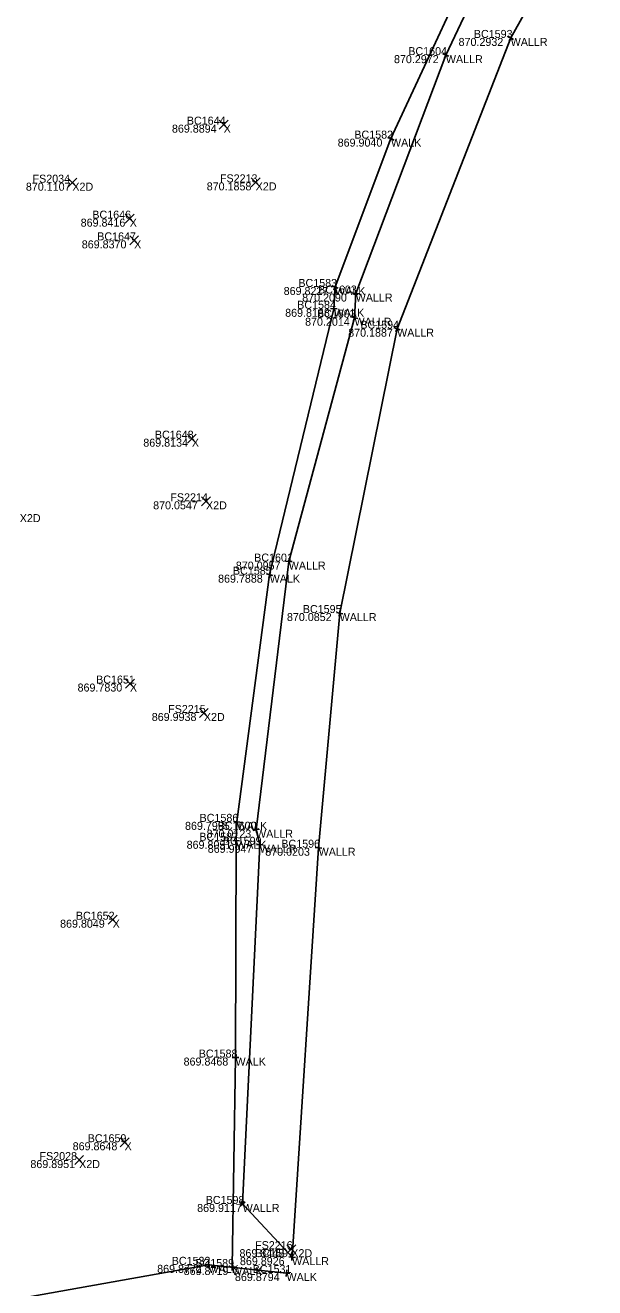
# Model space of a CAD drawing. Extents: x 1479425 to 1480294, y 379351 to 380102.
# Drawn here: x 1479699.88 to 1479704.14, y 379912.39 to 379921.85 of the extents above; entities that cross this region are included whole.
import ezdxf

# ---------------------------------------------------------------- set-up
doc = ezdxf.new("R2010")
doc.units = 0
for name, color, linetype in [('PV_X_Walk', 7, 'Continuous'), ('RD_X_Wall', 7, 'Continuous'), ('SV_X_Random_Point', 7, 'Continuous'), ('SV_X_Shot_Marker', 7, 'Continuous'), ('SV_X_Text_Comment', 7, 'Continuous'), ('SV_X_Text_Elevation', 7, 'Continuous'), ('SV_X_Text_Name', 7, 'Continuous')]:
    doc.layers.add(name, color=color, linetype=linetype)

msp = doc.modelspace()

# ---------------------------------------------------------------- linework, layer by layer
at = {"layer": 'PV_X_Walk'}
for points in [[(1479701.8352, 379912.4997), (1479701.2507, 379912.5611), (1479699.8235, 379912.3065), (1479697.4959, 379911.9204), (1479695.7834, 379911.7114), (1479695.8711, 379913.5546), (1479696.0253, 379915.6699), (1479696.3297, 379917.4434), (1479698.2528, 379916.8723), (1479698.3113, 379916.9697), (1479698.9161, 379918.9097), (1479698.892, 379918.9723), (1479699.4573, 379920.6485), (1479699.5018, 379920.7626), (1479697.5293, 379921.3818), (1479698.4277, 379923.2922)], [(1479703.3879, 379922.6665), (1479702.6175, 379921.0036), (1479702.1988, 379919.8915), (1479702.1896, 379919.7279), (1479701.7088, 379917.7349), (1479701.4627, 379915.8819), (1479701.457, 379915.7401), (1479701.4531, 379914.1148), (1479701.4276, 379912.5449)]]:
    msp.add_lwpolyline(points, dxfattribs=at)
at = {"layer": 'RD_X_Wall'}
msp.add_lwpolyline([(1479707.9477, 379927.6468), (1479706.4736, 379926.2425), (1479705.5301, 379925.1676), (1479704.7565, 379923.9768), (1479703.514, 379921.7583), (1479702.6632, 379919.5789), (1479702.2332, 379917.4471), (1479702.0758, 379915.6878), (1479701.8768, 379912.6189), (1479701.5063, 379913.0175), (1479701.6342, 379915.7099), (1479701.6071, 379915.8229), (1479701.8518, 379917.8328), (1479702.3444, 379919.6609), (1479702.3531, 379919.8421), (1479703.0284, 379921.6293), (1479703.7656, 379923.1882), (1479704.4556, 379924.2246), (1479704.5099, 379924.3288), (1479705.4153, 379925.6855), (1479706.4172, 379926.7904), (1479707.2828, 379927.6042)], dxfattribs=at)
at = {"layer": 'SV_X_Random_Point'}
for p, q in [((1479701.331, 379921.0749), (1479701.3976, 379921.1417)), ((1479701.331, 379921.1417), (1479701.3976, 379921.0749)), ((1479700.1977, 379920.6397), (1479700.2643, 379920.7065)), ((1479700.1977, 379920.7065), (1479700.2643, 379920.6397)), ((1479701.5707, 379920.6422), (1479701.6373, 379920.709)), ((1479701.5707, 379920.709), (1479701.6373, 379920.6422)), ((1479700.6275, 379920.3702), (1479700.6941, 379920.437)), ((1479700.6275, 379920.437), (1479700.6941, 379920.3702)), ((1479700.6603, 379920.2074), (1479700.7269, 379920.2742)), ((1479700.6603, 379920.2742), (1479700.7269, 379920.2074)), ((1479701.0928, 379918.7208), (1479701.1594, 379918.7876)), ((1479701.0928, 379918.7876), (1479701.1594, 379918.7208)), ((1479701.1987, 379918.2513), (1479701.2653, 379918.3181)), ((1479701.1987, 379918.3181), (1479701.2653, 379918.2513)), ((1479700.6289, 379916.8852), (1479700.6955, 379916.952)), ((1479700.6289, 379916.952), (1479700.6955, 379916.8852)), ((1479701.1827, 379916.6647), (1479701.2493, 379916.7315)), ((1479701.1827, 379916.7315), (1479701.2493, 379916.6647)), ((1479700.4993, 379915.1148), (1479700.5659, 379915.1816)), ((1479700.4993, 379915.1816), (1479700.5659, 379915.1148)), ((1479700.5889, 379913.4467), (1479700.6555, 379913.5135)), ((1479700.5889, 379913.5135), (1479700.6555, 379913.4467)), ((1479700.2487, 379913.3131), (1479700.3153, 379913.3799)), ((1479700.2487, 379913.3799), (1479700.3153, 379913.3131)), ((1479701.8377, 379912.6451), (1479701.9043, 379912.7119)), ((1479701.8377, 379912.7119), (1479701.9043, 379912.6451))]:
    msp.add_line(p, q, dxfattribs=at)
at = {"layer": 'SV_X_Shot_Marker'}
for p, q in [((1479703.5358, 379921.7461), (1479703.4922, 379921.7705)), ((1479703.5262, 379921.7801), (1479703.5018, 379921.7365)), ((1479703.514, 379921.7583), (1479703.514, 379921.7583)), ((1479703.005, 379921.6382), (1479703.0518, 379921.6205)), ((1479703.0196, 379921.6059), (1479703.0372, 379921.6527)), ((1479703.0284, 379921.6293), (1479703.0284, 379921.6293)), ((1479702.6402, 379920.9931), (1479702.5948, 379921.0141)), ((1479702.628, 379921.0263), (1479702.607, 379920.9809)), ((1479702.6175, 379921.0036), (1479702.6175, 379921.0036)), ((1479702.2222, 379919.8827), (1479702.1754, 379919.9003)), ((1479702.2076, 379919.9149), (1479702.19, 379919.8681)), ((1479702.1988, 379919.8915), (1479702.1988, 379919.8915)), ((1479702.3281, 379919.8433), (1479702.3781, 379919.8409)), ((1479702.3519, 379919.8171), (1479702.3543, 379919.8671)), ((1479702.3531, 379919.8421), (1479702.3531, 379919.8421)), ((1479702.191, 379919.7529), (1479702.1882, 379919.703)), ((1479702.2146, 379919.7265), (1479702.1646, 379919.7293)), ((1479702.1896, 379919.7279), (1479702.1896, 379919.7279)), ((1479702.3203, 379919.6674), (1479702.3685, 379919.6544)), ((1479702.3379, 379919.6368), (1479702.3509, 379919.6851)), ((1479702.3444, 379919.6609), (1479702.3444, 379919.6609)), ((1479702.6865, 379919.5698), (1479702.6399, 379919.588)), ((1479702.6723, 379919.6022), (1479702.6541, 379919.5556)), ((1479702.6632, 379919.5789), (1479702.6632, 379919.5789)), ((1479701.8488, 379917.808), (1479701.8548, 379917.8576)), ((1479701.7147, 379917.7592), (1479701.7029, 379917.7106)), ((1479701.827, 379917.8358), (1479701.8766, 379917.8298)), ((1479701.8518, 379917.8328), (1479701.8518, 379917.8328)), ((1479701.7331, 379917.7291), (1479701.6845, 379917.7408)), ((1479701.7088, 379917.7349), (1479701.7088, 379917.7349)), ((1479702.2381, 379917.4716), (1479702.2283, 379917.4226)), ((1479702.2577, 379917.4422), (1479702.2087, 379917.4521)), ((1479702.2332, 379917.4471), (1479702.2332, 379917.4471)), ((1479701.4875, 379915.8786), (1479701.4379, 379915.8852)), ((1479701.466, 379915.9067), (1479701.4594, 379915.8571)), ((1479701.4627, 379915.8819), (1479701.4627, 379915.8819)), ((1479701.458, 379915.7651), (1479701.456, 379915.7151)), ((1479701.5828, 379915.8171), (1479701.6314, 379915.8287)), ((1479701.6129, 379915.7986), (1479701.6013, 379915.8472)), ((1479701.6071, 379915.8229), (1479701.6071, 379915.8229)), ((1479701.482, 379915.7391), (1479701.432, 379915.7411)), ((1479701.457, 379915.7401), (1479701.457, 379915.7401)), ((1479701.6092, 379915.7111), (1479701.6592, 379915.7087)), ((1479701.633, 379915.6849), (1479701.6354, 379915.7349)), ((1479701.6342, 379915.7099), (1479701.6342, 379915.7099)), ((1479702.1007, 379915.6856), (1479702.0509, 379915.69)), ((1479702.078, 379915.7127), (1479702.0736, 379915.6629)), ((1479702.0758, 379915.6878), (1479702.0758, 379915.6878)), ((1479701.4781, 379914.1148), (1479701.4281, 379914.1149)), ((1479701.4532, 379914.1398), (1479701.453, 379914.0898)), ((1479701.4531, 379914.1148), (1479701.4531, 379914.1148)), ((1479701.488, 379913.0005), (1479701.5246, 379913.0345)), ((1479701.5233, 379912.9992), (1479701.4893, 379913.0358)), ((1479701.5063, 379913.0175), (1479701.5063, 379913.0175)), ((1479701.8784, 379912.6439), (1479701.8752, 379912.594)), ((1479701.2756, 379912.5585), (1479701.2258, 379912.5637)), ((1479701.2481, 379912.5363), (1479701.2533, 379912.586)), ((1479701.2507, 379912.5611), (1479701.2507, 379912.5611)), ((1479701.4526, 379912.5445), (1479701.4026, 379912.5453)), ((1479701.428, 379912.5699), (1479701.4272, 379912.5199)), ((1479701.4276, 379912.5449), (1479701.4276, 379912.5449)), ((1479701.9017, 379912.6173), (1479701.8518, 379912.6205)), ((1479701.8768, 379912.6189), (1479701.8768, 379912.6189)), ((1479701.8601, 379912.4971), (1479701.8103, 379912.5023)), ((1479701.8326, 379912.4749), (1479701.8378, 379912.5246)), ((1479701.8352, 379912.4997), (1479701.8352, 379912.4997))]:
    msp.add_line(p, q, dxfattribs=at)

# ---------------------------------------------------------------- texts
at = {"layer": 'SV_X_Text_Comment'}
for s, p in [('WALLR', (1479703.514, 379921.6983)), ('WALLR', (1479703.0284, 379921.5693)), ('X', (1479701.3643, 379921.0483)), ('WALK', (1479702.6175, 379920.9436)), ('X2D', (1479700.231, 379920.6131)), ('X2D', (1479701.604, 379920.6156)), ('X', (1479700.6608, 379920.3436)), ('X', (1479700.6936, 379920.1808)), ('WALK', (1479702.1988, 379919.8315)), ('WALLR', (1479702.3531, 379919.7821)), ('WALK', (1479702.1896, 379919.6679)), ('WALLR', (1479702.3444, 379919.6009)), ('WALLR', (1479702.6632, 379919.5189)), ('X', (1479701.1261, 379918.6942)), ('X2D', (1479701.232, 379918.2247)), ('X2D', (1479699.837, 379918.1286)), ('WALLR', (1479701.8518, 379917.7728)), ('WALK', (1479701.7088, 379917.6749)), ('WALLR', (1479702.2332, 379917.3871)), ('X', (1479700.6622, 379916.8586)), ('X2D', (1479701.216, 379916.6381)), ('WALK', (1479701.4627, 379915.8219)), ('WALLR', (1479701.6071, 379915.7629)), ('WALK', (1479701.457, 379915.6801)), ('WALLR', (1479701.6342, 379915.6499)), ('WALLR', (1479702.0758, 379915.6278)), ('X', (1479700.5326, 379915.0882)), ('WALK', (1479701.4531, 379914.0548)), ('X', (1479700.6222, 379913.4201)), ('X2D', (1479700.282, 379913.2865)), ('WALLR', (1479701.5063, 379912.9575)), ('X2D', (1479701.871, 379912.6185)), ('WALK', (1479701.2507, 379912.5011)), ('WALK', (1479701.4276, 379912.4849)), ('WALLR', (1479701.8768, 379912.5589)), ('WALK', (1479701.8352, 379912.4397))]:
    msp.add_text(s, height=0.06, dxfattribs=at).set_placement(p)
at = {"layer": 'SV_X_Text_Elevation'}
for s, p in [('870.2932', (1479703.1238, 379921.6983)), ('870.2972', (1479702.6401, 379921.5693)), ('869.8894', (1479700.9769, 379921.0483)), ('869.9040', (1479702.2183, 379920.9436)), ('870.1107', (1479699.8829, 379920.6131)), ('870.1858', (1479701.2374, 379920.6156)), ('869.8416', (1479700.2933, 379920.3436)), ('869.8370', (1479700.3015, 379920.1808)), ('869.8227', (1479701.8138, 379919.8315)), ('870.2090', (1479701.9525, 379919.7821)), ('869.8168', (1479701.8249, 379919.6679)), ('870.2014', (1479701.9741, 379919.6009)), ('870.1887', (1479702.2971, 379919.5189)), ('869.8134', (1479700.7624, 379918.6942)), ('870.0547', (1479700.8361, 379918.2247)), ('870.0957', (1479701.4554, 379917.7728)), ('869.7888', (1479701.3224, 379917.6749)), ('870.0852', (1479701.8383, 379917.3871)), ('869.7830', (1479700.2701, 379916.8586)), ('869.9938', (1479700.8258, 379916.6381)), ('869.7995', (1479701.0748, 379915.8219)), ('870.0123', (1479701.2363, 379915.7629)), ('869.8051', (1479701.087, 379915.6801)), ('869.9947', (1479701.2449, 379915.6499)), ('870.0203', (1479701.6757, 379915.6278)), ('869.8049', (1479700.1391, 379915.0882)), ('869.8468', (1479701.0643, 379914.0548)), ('869.8648', (1479700.2334, 379913.4201)), ('869.8951', (1479699.9167, 379913.2865)), ('869.9117', (1479701.1657, 379912.9575)), ('869.8448', (1479701.4827, 379912.6185)), ('869.8772', (1479700.8662, 379912.5011)), ('869.8719', (1479701.0649, 379912.4849)), ('869.8926', (1479701.4861, 379912.5589)), ('869.8794', (1479701.4488, 379912.4397))]:
    msp.add_text(s, height=0.06, dxfattribs=at).set_placement(p)
at = {"layer": 'SV_X_Text_Name'}
for s, p in [('BC1593', (1479703.2381, 379921.7583)), ('BC1604', (1479702.7473, 379921.6293)), ('BC1644', (1479701.0884, 379921.1083)), ('BC1582', (1479702.3431, 379921.0036)), ('FS2034', (1479699.9329, 379920.6731)), ('FS2213', (1479701.3366, 379920.6756)), ('BC1646', (1479700.3807, 379920.4036)), ('BC1647', (1479700.4173, 379920.2408)), ('BC1583', (1479701.9239, 379919.8915)), ('BC1603', (1479702.0716, 379919.8421)), ('BC1584', (1479701.9152, 379919.7279)), ('BC1602', (1479702.0633, 379919.6609)), ('BC1594', (1479702.3878, 379919.5789)), ('BC1648', (1479700.8493, 379918.7542)), ('FS2214', (1479700.9651, 379918.2847)), ('BC1601', (1479701.5928, 379917.8328)), ('BC1585', (1479701.4339, 379917.7349)), ('BC1595', (1479701.9573, 379917.4471)), ('BC1651', (1479700.4089, 379916.9186)), ('FS2215', (1479700.9486, 379916.6981)), ('BC1586', (1479701.184, 379915.8819)), ('BC1600', (1479701.3204, 379915.8229)), ('BC1587', (1479701.1821, 379915.7401)), ('BC1599', (1479701.3579, 379915.7099)), ('BC1596', (1479701.7962, 379915.6878)), ('BC1652', (1479700.2572, 379915.1482)), ('BC1588', (1479701.1777, 379914.1148)), ('BC1659', (1479700.3459, 379913.4801)), ('FS2028', (1479699.9849, 379913.3465)), ('BC1598', (1479701.23, 379913.0175)), ('FS2216', (1479701.5999, 379912.6785)), ('BC1597', (1479701.6009, 379912.6189)), ('BC1532', (1479700.9753, 379912.5611)), ('BC1589', (1479701.1523, 379912.5449)), ('BC1531', (1479701.5819, 379912.4997))]:
    msp.add_text(s, height=0.06, dxfattribs=at).set_placement(p)

doc.saveas('drawing.dxf')
